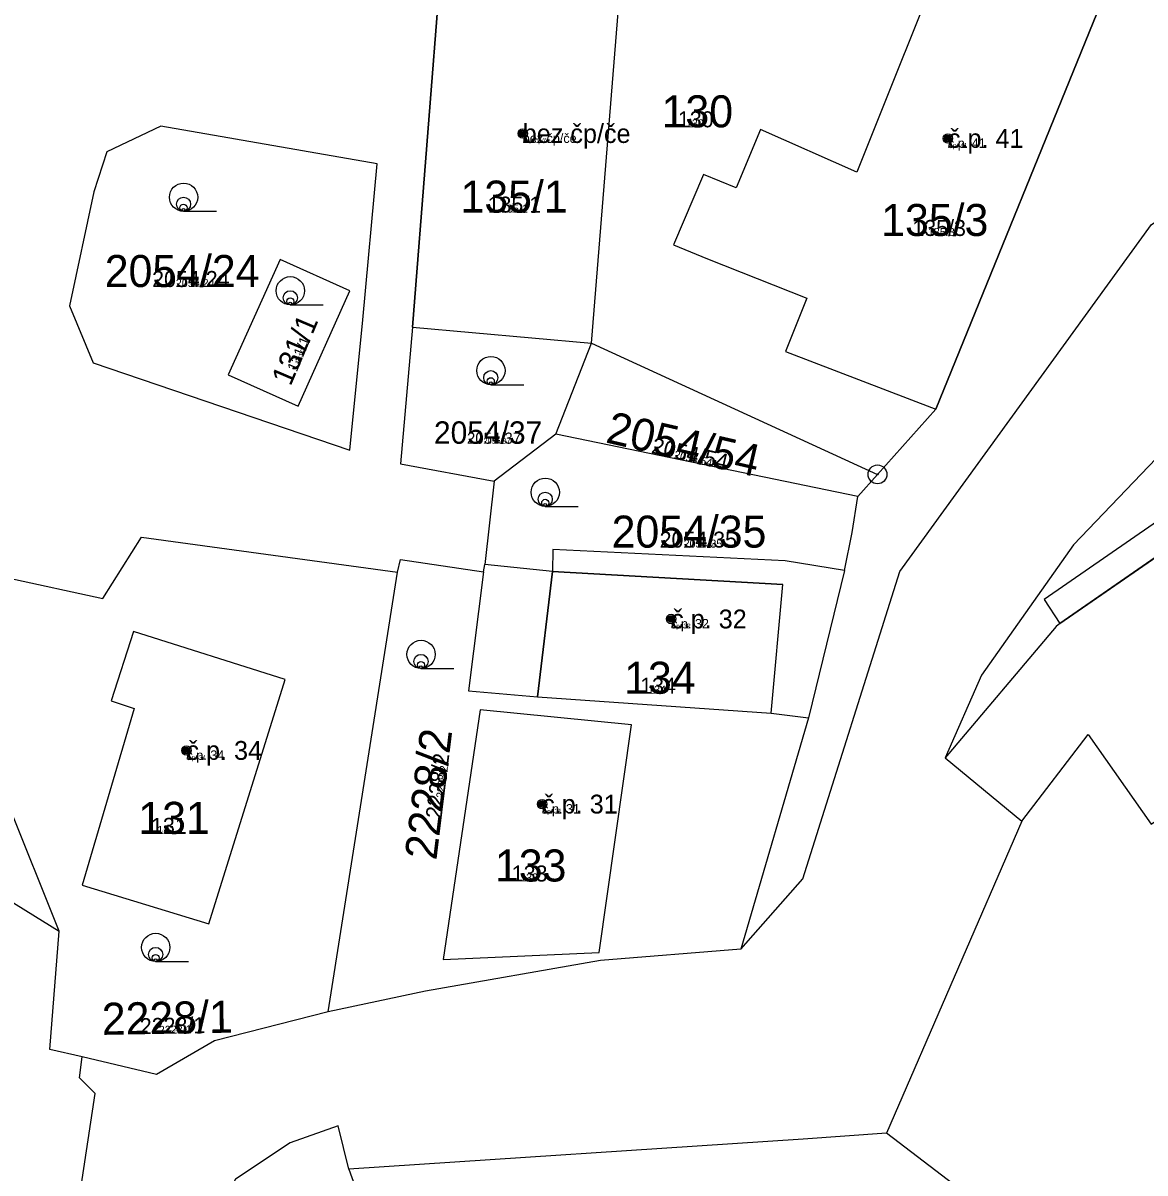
# Model space of a CAD drawing. Extents: x -744652 to -739090, y -980828 to -975855.
# Drawn here: x -742552.9 to -742493.3, y -978772.2 to -978711.1 of the extents above; entities that cross this region are included whole.
import ezdxf

# ---------------------------------------------------------------- set-up
doc = ezdxf.new("R2010")
doc.units = 0
for name, color, linetype in [('KAT_02_hranice parcel', 7, 'Continuous'), ('KAT_03_1000_st čísla parcelní', 7, 'Continuous'), ('KAT_03_1000_čísla parcelní', 7, 'Continuous'), ('KAT_03_1000_čísla popisná', 7, 'Continuous'), ('KAT_03_100_st čísla parcelní', 7, 'Continuous'), ('KAT_03_100_čísla parcelní', 7, 'Continuous'), ('KAT_03_100_čísla popisná', 7, 'Continuous'), ('KAT_03_250_st čísla parcelní', 7, 'Continuous'), ('KAT_03_250_čísla parcelní', 7, 'Continuous'), ('KAT_03_250_čísla popisná', 7, 'Continuous'), ('KAT_03_500_st čísla parcelní', 7, 'Continuous'), ('KAT_03_500_čísla parcelní', 7, 'Continuous'), ('KAT_03_500_čísla popisná', 7, 'Continuous'), ('KAT_04_vnitřní kresba', 7, 'Continuous'), ('KAT_05_1000_značky kultur', 7, 'Continuous'), ('KAT_05_100_značky kultur', 7, 'Continuous'), ('KAT_05_250_značky kultur', 7, 'Continuous'), ('KAT_05_500_značky kultur', 7, 'Continuous'), ('KAT_07_1000_značky budov', 7, 'Continuous'), ('KAT_07_100_značky budov', 7, 'Continuous'), ('KAT_07_500_značky budov', 7, 'Continuous'), ('KAT_11_značky bodu BP', 7, 'Continuous'), ('KAT_14_plocha_budovy', 7, 'Continuous')]:
    doc.layers.add(name, color=color, linetype=linetype)

msp = doc.modelspace()

# ---------------------------------------------------------------- linework, layer by layer
at = {"layer": 'KAT_02_hranice parcel'}
for p, q in [((-742532.24, -978727.28), (-742522.73, -978728.12)), ((-742524.62, -978732.95), (-742522.73, -978728.12)), ((-742522.73, -978728.12), (-742507.54, -978735.09)), ((-742507.54, -978735.09), (-742504.45, -978731.62)), ((-742524.62, -978732.95), (-742527.89, -978735.45)), ((-742508.58, -978736.26), (-742524.62, -978732.95)), ((-742508.58, -978736.26), (-742507.54, -978735.09)), ((-742527.89, -978735.45), (-742528.39, -978739.87)), ((-742528.47, -978740.27), (-742528.39, -978739.87)), ((-742536.72, -978763.63), (-742533.03, -978740.29)), ((-742509.3, -978740.19), (-742511.21, -978748.02)), ((-742511.21, -978748.02), (-742514.8, -978760.31)), ((-742503.95, -978750.15), (-742499.87, -978753.51)), ((-742499.87, -978753.51), (-742507.07, -978770.07)), ((-742554.18, -978757.39), (-742551, -978759.35)), ((-742488.77, -978784.01), (-742507.07, -978770.07)), ((-742535.61, -978771.98), (-742535.04, -978773.56))]:
    msp.add_line(p, q, dxfattribs=at)
for points in [[(-742514.8, -978760.31), (-742511.5, -978756.57), (-742506.35, -978740.24), (-742492.99, -978721.82), (-742477.74, -978711.95), (-742471.84, -978709.6), (-742471.81, -978707.76), (-742469.88, -978707.71), (-742450.51, -978700.27), (-742428.19, -978701.36), (-742428.2, -978700.54), (-742414.74, -978703.02)], [(-742503.55, -978706.34), (-742508.63, -978719.04), (-742513.76, -978716.77), (-742515.05, -978719.88), (-742516.78, -978719.16), (-742518.38, -978722.9), (-742516.57, -978723.65), (-742511.29, -978725.73), (-742512.43, -978728.57), (-742504.45, -978731.62)], [(-742503.55, -978706.34), (-742495.47, -978709.56), (-742504.45, -978731.62)], [(-742532.24, -978727.28), (-742530.72, -978707.92), (-742521.51, -978708.77)], [(-742522.73, -978728.12), (-742521.17, -978708.79), (-742521.51, -978708.77)], [(-742534.88, -978726.89), (-742534.12, -978718.6), (-742545.6, -978716.59), (-742548.46, -978717.96), (-742549.16, -978720.09), (-742550.45, -978726.14), (-742549.19, -978729.17), (-742535.56, -978733.81), (-742534.88, -978726.89)], [(-742470.25, -978719.38), (-742489.15, -978730.49), (-742497.14, -978738.84), (-742502.01, -978745.76), (-742503.95, -978750.15)], [(-742542.02, -978729.8), (-742538.31, -978731.47), (-742535.56, -978725.35), (-742539.27, -978723.68), (-742542.02, -978729.8)], [(-742465.82, -978724.74), (-742483.41, -978733.01), (-742484.4, -978733.67), (-742485.39, -978733.31), (-742486.83, -978733.72), (-742487.62, -978734.81), (-742487.68, -978735.97), (-742488.66, -978736.64), (-742489.52, -978735.39), (-742498.69, -978741.74), (-742497.86, -978743.01), (-742498.06, -978743.17), (-742503.95, -978750.15)], [(-742532.24, -978727.28), (-742532.87, -978734.53), (-742527.89, -978735.45)], [(-742499.87, -978753.51), (-742496.36, -978748.91), (-742493.01, -978753.67), (-742491.55, -978752.65), (-742480.55, -978768.62), (-742477.06, -978766.25), (-742476.32, -978767.3), (-742461.67, -978757.32), (-742471.99, -978742.58), (-742468.05, -978739.81), (-742463.71, -978737.68), (-742465.34, -978734.17), (-742463.7, -978728.64)], [(-742509.3, -978740.19), (-742508.88, -978738.17), (-742508.58, -978736.26)], [(-742551, -978759.35), (-742553.71, -978752.59), (-742554.39, -978748.63), (-742554.26, -978744.59), (-742553.72, -978740.59), (-742548.68, -978741.69), (-742546.62, -978738.42), (-742533.03, -978740.29)], [(-742509.3, -978740.19), (-742512.44, -978739.69), (-742524.78, -978739.08), (-742524.8, -978740.24), (-742528.39, -978739.87)], [(-742533.03, -978740.29), (-742532.87, -978739.61), (-742528.47, -978740.27)], [(-742528.47, -978740.27), (-742529.27, -978746.58), (-742525.59, -978746.9), (-742513.18, -978747.77), (-742511.21, -978748.02)], [(-742543.06, -978758.96), (-742539, -978745.98), (-742547.06, -978743.44), (-742548.24, -978747.11), (-742547.01, -978747.52), (-742549.77, -978756.9), (-742543.06, -978758.96)], [(-742520.61, -978748.39), (-742528.65, -978747.6), (-742530.61, -978760.86), (-742522.32, -978760.48), (-742520.61, -978748.39)], [(-742549.77, -978766.02), (-742551.5, -978765.64), (-742551, -978759.35)], [(-742514.8, -978760.31), (-742522.26, -978760.91), (-742531.54, -978762.54), (-742536.72, -978763.63)], [(-742536.72, -978763.63), (-742542.75, -978765.17), (-742545.83, -978766.96), (-742549.77, -978766.02)], [(-742550.52, -978777.46), (-742549.08, -978767.97), (-742549.92, -978767.13), (-742549.77, -978766.02)], [(-742535.61, -978771.98), (-742536.18, -978769.68), (-742538.73, -978770.59), (-742541.64, -978772.51), (-742542.72, -978774.57), (-742543.19, -978780.54), (-742542.48, -978785.35), (-742540.01, -978797.95), (-742544.04, -978799.67), (-742552.42, -978804.18), (-742552.86, -978804.25), (-742557.61, -978803.13), (-742558.73, -978802.65)], [(-742507.07, -978770.07), (-742511.49, -978770.39), (-742535.61, -978771.98)]]:
    msp.add_lwpolyline(points, dxfattribs=at)
at = {"layer": 'KAT_03_1000_čísla popisná'}
for centre in [(-742526.38, -978716.99), (-742526.38, -978716.99), (-742503.8, -978717.25), (-742503.8, -978717.25), (-742518.5, -978742.77), (-742518.5, -978742.77), (-742544.24, -978749.75), (-742544.24, -978749.75), (-742525.35, -978752.6), (-742525.35, -978752.6)]:
    msp.add_circle(centre, 0.25, dxfattribs=at)
at = {"layer": 'KAT_03_100_čísla popisná'}
for centre in [(-742526.38, -978716.99), (-742526.38, -978716.99), (-742503.8, -978717.25), (-742503.8, -978717.25), (-742518.5, -978742.77), (-742518.5, -978742.77), (-742544.24, -978749.75), (-742544.24, -978749.75), (-742525.35, -978752.6), (-742525.35, -978752.6)]:
    msp.add_circle(centre, 0.025, dxfattribs=at)
at = {"layer": 'KAT_03_250_čísla popisná'}
for centre in [(-742526.38, -978716.99), (-742526.38, -978716.99), (-742503.8, -978717.25), (-742503.8, -978717.25), (-742518.5, -978742.77), (-742518.5, -978742.77), (-742544.24, -978749.75), (-742544.24, -978749.75), (-742525.35, -978752.6), (-742525.35, -978752.6)]:
    msp.add_circle(centre, 0.0625, dxfattribs=at)
at = {"layer": 'KAT_03_500_čísla popisná'}
for centre in [(-742526.38, -978716.99), (-742526.38, -978716.99), (-742503.8, -978717.25), (-742503.8, -978717.25), (-742518.5, -978742.77), (-742518.5, -978742.77), (-742544.24, -978749.75), (-742544.24, -978749.75), (-742525.35, -978752.6), (-742525.35, -978752.6)]:
    msp.add_circle(centre, 0.125, dxfattribs=at)
at = {"layer": 'KAT_04_vnitřní kresba'}
for p, q in [((-742497.86, -978743.01), (-742488.66, -978736.64)), ((-742525.59, -978746.9), (-742524.8, -978740.24)), ((-742524.8, -978740.24), (-742512.56, -978740.94)), ((-742513.18, -978747.77), (-742512.56, -978740.94))]:
    msp.add_line(p, q, dxfattribs=at)
at = {"layer": 'KAT_05_1000_značky kultur'}
for p, q in [((-742544.393, -978721.12), (-742542.643, -978721.12)), ((-742538.723, -978726.09), (-742536.973, -978726.09)), ((-742528.073, -978730.33), (-742526.323, -978730.33)), ((-742525.183, -978736.79), (-742523.433, -978736.79)), ((-742531.783, -978745.4), (-742530.033, -978745.4)), ((-742545.873, -978760.96), (-742544.123, -978760.96))]:
    msp.add_line(p, q, dxfattribs=at)
for centre in [(-742544.393, -978720.37), (-742538.723, -978725.34), (-742528.073, -978729.58), (-742525.183, -978736.04), (-742531.783, -978744.65), (-742545.873, -978760.21)]:
    msp.add_circle(centre, 0.75, dxfattribs=at)
at = {"layer": 'KAT_05_100_značky kultur'}
for p, q in [((-742544.399, -978721.12), (-742544.224, -978721.12)), ((-742538.729, -978726.09), (-742538.554, -978726.09)), ((-742528.079, -978730.33), (-742527.904, -978730.33)), ((-742525.189, -978736.79), (-742525.014, -978736.79)), ((-742531.789, -978745.4), (-742531.614, -978745.4)), ((-742545.879, -978760.96), (-742545.704, -978760.96))]:
    msp.add_line(p, q, dxfattribs=at)
for centre in [(-742544.399, -978721.045), (-742538.729, -978726.015), (-742528.079, -978730.255), (-742525.189, -978736.715), (-742531.789, -978745.325), (-742545.879, -978760.885)]:
    msp.add_circle(centre, 0.075, dxfattribs=at)
at = {"layer": 'KAT_05_250_značky kultur'}
for p, q in [((-742544.398, -978721.12), (-742543.961, -978721.12)), ((-742538.728, -978726.09), (-742538.291, -978726.09)), ((-742528.078, -978730.33), (-742527.641, -978730.33)), ((-742525.188, -978736.79), (-742524.751, -978736.79)), ((-742531.788, -978745.4), (-742531.351, -978745.4)), ((-742545.878, -978760.96), (-742545.441, -978760.96))]:
    msp.add_line(p, q, dxfattribs=at)
for centre in [(-742544.398, -978720.932), (-742538.728, -978725.902), (-742528.078, -978730.142), (-742525.188, -978736.602), (-742531.788, -978745.212), (-742545.878, -978760.772)]:
    msp.add_circle(centre, 0.187, dxfattribs=at)
at = {"layer": 'KAT_05_500_značky kultur'}
for p, q in [((-742544.397, -978721.12), (-742543.522, -978721.12)), ((-742538.726, -978726.09), (-742537.851, -978726.09)), ((-742528.076, -978730.33), (-742527.201, -978730.33)), ((-742525.187, -978736.79), (-742524.312, -978736.79)), ((-742531.787, -978745.4), (-742530.912, -978745.4)), ((-742545.877, -978760.96), (-742545.002, -978760.96))]:
    msp.add_line(p, q, dxfattribs=at)
for centre in [(-742544.396, -978720.745), (-742538.726, -978725.715), (-742528.076, -978729.955), (-742525.186, -978736.415), (-742531.786, -978745.025), (-742545.876, -978760.585)]:
    msp.add_circle(centre, 0.375, dxfattribs=at)
at = {"layer": 'KAT_07_1000_značky budov'}
for centre in [(-742526.387, -978716.989), (-742503.807, -978717.249), (-742518.507, -978742.769), (-742544.247, -978749.749), (-742525.357, -978752.599)]:
    msp.add_circle(centre, 0.175, dxfattribs=at)
at = {"layer": 'KAT_07_100_značky budov'}
for centre in [(-742526.381, -978716.99), (-742503.801, -978717.25), (-742518.501, -978742.77), (-742544.241, -978749.75), (-742525.351, -978752.6)]:
    msp.add_circle(centre, 0.0175, dxfattribs=at)
at = {"layer": 'KAT_07_500_značky budov'}
for centre, radius in [((-742526.383, -978716.99), 0.0875), ((-742526.382, -978716.99), 0.0438), ((-742503.803, -978717.25), 0.0875), ((-742503.802, -978717.25), 0.0438), ((-742518.503, -978742.77), 0.0875), ((-742518.502, -978742.77), 0.0438), ((-742544.243, -978749.75), 0.0875), ((-742544.242, -978749.75), 0.0438), ((-742525.353, -978752.6), 0.0875), ((-742525.352, -978752.6), 0.0438)]:
    msp.add_circle(centre, radius, dxfattribs=at)
at = {"layer": 'KAT_11_značky bodu BP'}
for radius in [0.5, 0.0303]:
    msp.add_circle((-742507.54, -978735.09), radius, dxfattribs=at)
at = {"layer": 'KAT_14_plocha_budovy'}
for points in [[(-742516.78, -978719.16), (-742518.38, -978722.9), (-742516.57, -978723.65), (-742511.29, -978725.73), (-742512.43, -978728.57), (-742504.45, -978731.62), (-742495.47, -978709.56), (-742503.55, -978706.34), (-742508.63, -978719.04), (-742513.76, -978716.77), (-742515.05, -978719.88)], [(-742532.24, -978727.28), (-742522.73, -978728.12), (-742521.17, -978708.79), (-742521.51, -978708.77), (-742530.72, -978707.92)], [(-742503.95, -978750.15), (-742499.87, -978753.51), (-742496.36, -978748.91), (-742493.01, -978753.67), (-742491.55, -978752.65), (-742480.55, -978768.62), (-742477.06, -978766.25), (-742465.79, -978758.54), (-742483.41, -978733.01), (-742484.4, -978733.67), (-742485.39, -978733.31), (-742486.83, -978733.72), (-742487.62, -978734.81), (-742487.68, -978735.97), (-742488.66, -978736.64), (-742497.86, -978743.01), (-742498.06, -978743.17)], [(-742525.59, -978746.9), (-742513.18, -978747.77), (-742512.56, -978740.94), (-742524.8, -978740.24)], [(-742549.77, -978756.9), (-742543.06, -978758.96), (-742539, -978745.98), (-742547.06, -978743.44), (-742548.24, -978747.11), (-742547.01, -978747.52)], [(-742530.61, -978760.86), (-742522.32, -978760.48), (-742520.61, -978748.39), (-742528.65, -978747.6)]]:
    msp.add_lwpolyline(points, close=True, dxfattribs=at)

# ---------------------------------------------------------------- texts
at = {"layer": 'KAT_03_1000_st čísla parcelní'}
for s, p in [('135/1', (-742529.683, -978721.19)), ('135/3', (-742507.343, -978722.43)), ('134', (-742520.994, -978746.74)), ('131', (-742546.794, -978754.18)), ('133', (-742527.854, -978756.71))]:
    msp.add_text(s, height=1.7, dxfattribs=at).set_placement(p)
at = {"layer": 'KAT_03_1000_čísla parcelní'}
for s, height, p in [('130', 1.7, (-742519.004, -978716.66)), ('2054/24', 1.7, (-742548.578, -978725.14)), ('2054/37', 1.19, (-742531.096, -978733.465)), ('2054/35', 1.7, (-742521.658, -978738.98))]:
    msp.add_text(s, height=height, dxfattribs=at).set_placement(p)
for s, height, rotation, p in [('131/1', 1.14, 67, (-742538.711, -978730.444)), ('2054/54', 1.7, 347, (-742522.03, -978733.384)), ('2228/2', 1.7, 83, (-742530.969, -978755.614)), ('2228/1', 1.7, 1, (-742548.72, -978764.857))]:
    msp.add_text(s, height=height, rotation=rotation, dxfattribs=at).set_placement(p)
at = {"layer": 'KAT_03_1000_čísla popisná'}
for s, height, p in [('bez čp/če', 1, (-742526.38, -978717.49)), ('č.p. 41', 1, (-742503.8, -978717.75)), ('135/1', 0.017, (-742526.841, -978721.19)), ('135/3', 0.017, (-742504.07, -978722.43)), ('č.p. 32', 1, (-742518.5, -978743.27)), ('134', 0.017, (-742519.318, -978746.74)), ('č.p. 34', 1, (-742544.24, -978750.25)), ('č.p. 31', 1, (-742525.35, -978753.1)), ('131', 0.017, (-742545.462, -978754.18)), ('133', 0.017, (-742526.092, -978756.71))]:
    msp.add_text(s, height=height, dxfattribs=at).set_placement(p)
at = {"layer": 'KAT_03_100_st čísla parcelní'}
for s, p in [('135/1', (-742527.099, -978721.19)), ('135/3', (-742504.368, -978722.43)), ('134', (-742519.47, -978746.74)), ('131', (-742545.583, -978754.18)), ('133', (-742526.252, -978756.71))]:
    msp.add_text(s, height=0.17, dxfattribs=at).set_placement(p)
at = {"layer": 'KAT_03_100_čísla parcelní'}
for s, height, p in [('130', 0.17, (-742517.456, -978716.66)), ('2054/24', 0.17, (-742544.049, -978725.14)), ('2054/37', 0.119, (-742527.942, -978733.465)), ('2054/35', 0.17, (-742517.074, -978738.98))]:
    msp.add_text(s, height=height, dxfattribs=at).set_placement(p)
for s, height, rotation, p in [('131/1', 0.114, 67, (-742538.127, -978729.068)), ('2054/54', 0.17, 347, (-742517.64, -978734.397)), ('2228/2', 0.17, 83, (-742530.482, -978751.644)), ('2228/1', 0.17, 1, (-742545.101, -978764.794))]:
    msp.add_text(s, height=height, rotation=rotation, dxfattribs=at).set_placement(p)
at = {"layer": 'KAT_03_100_čísla popisná'}
for s, height, p in [('bez čp/če', 0.1, (-742526.38, -978717.49)), ('č.p. 41', 0.1, (-742503.8, -978717.75)), ('135/1', 0.0017, (-742526.815, -978721.19)), ('135/3', 0.0017, (-742504.04, -978722.43)), ('č.p. 32', 0.1, (-742518.5, -978743.27)), ('134', 0.0017, (-742519.303, -978746.74)), ('č.p. 34', 0.1, (-742544.24, -978750.25)), ('č.p. 31', 0.1, (-742525.35, -978753.1)), ('131', 0.0017, (-742545.45, -978754.18)), ('133', 0.0017, (-742526.076, -978756.71))]:
    msp.add_text(s, height=height, dxfattribs=at).set_placement(p)
at = {"layer": 'KAT_03_250_st čísla parcelní'}
for s, p in [('135/1', (-742527.53, -978721.19)), ('135/3', (-742504.863, -978722.43)), ('134', (-742519.724, -978746.74)), ('131', (-742545.785, -978754.18)), ('133', (-742526.519, -978756.71))]:
    msp.add_text(s, height=0.425, dxfattribs=at).set_placement(p)
at = {"layer": 'KAT_03_250_čísla parcelní'}
for s, height, p in [('130', 0.425, (-742517.714, -978716.66)), ('2054/24', 0.425, (-742544.804, -978725.14)), ('2054/37', 0.2975, (-742528.468, -978733.465)), ('2054/35', 0.425, (-742517.838, -978738.98))]:
    msp.add_text(s, height=height, dxfattribs=at).set_placement(p)
for s, height, rotation, p in [('131/1', 0.285, 67, (-742538.224, -978729.298)), ('2054/54', 0.425, 347, (-742518.372, -978734.229)), ('2228/2', 0.425, 83, (-742530.563, -978752.306)), ('2228/1', 0.425, 1, (-742545.704, -978764.804))]:
    msp.add_text(s, height=height, rotation=rotation, dxfattribs=at).set_placement(p)
at = {"layer": 'KAT_03_250_čísla popisná'}
for s, height, p in [('bez čp/če', 0.25, (-742526.38, -978717.49)), ('č.p. 41', 0.25, (-742503.8, -978717.75)), ('135/1', 0.00425, (-742526.819, -978721.19)), ('135/3', 0.00425, (-742504.045, -978722.43)), ('č.p. 32', 0.25, (-742518.5, -978743.27)), ('134', 0.00425, (-742519.305, -978746.74)), ('č.p. 34', 0.25, (-742544.24, -978750.25)), ('č.p. 31', 0.25, (-742525.35, -978753.1)), ('131', 0.00425, (-742545.452, -978754.18)), ('133', 0.00425, (-742526.078, -978756.71))]:
    msp.add_text(s, height=height, dxfattribs=at).set_placement(p)
at = {"layer": 'KAT_03_500_st čísla parcelní'}
for s, p in [('135/1', (-742528.247, -978721.19)), ('135/3', (-742505.69, -978722.43)), ('134', (-742520.147, -978746.74)), ('131', (-742546.121, -978754.18)), ('133', (-742526.964, -978756.71))]:
    msp.add_text(s, height=0.85, dxfattribs=at).set_placement(p)
at = {"layer": 'KAT_03_500_čísla parcelní'}
for s, height, p in [('130', 0.85, (-742518.144, -978716.66)), ('2054/24', 0.85, (-742546.062, -978725.14)), ('2054/37', 0.595, (-742529.344, -978733.465)), ('2054/35', 0.85, (-742519.112, -978738.98))]:
    msp.add_text(s, height=height, dxfattribs=at).set_placement(p)
for s, height, rotation, p in [('131/1', 0.57, 67, (-742538.387, -978729.68)), ('2054/54', 0.85, 347, (-742519.591, -978733.947)), ('2228/2', 0.85, 83, (-742530.698, -978753.409)), ('2228/1', 0.85, 1, (-742546.709, -978764.822))]:
    msp.add_text(s, height=height, rotation=rotation, dxfattribs=at).set_placement(p)
at = {"layer": 'KAT_03_500_čísla popisná'}
for s, height, p in [('bez čp/če', 0.5, (-742526.38, -978717.49)), ('č.p. 41', 0.5, (-742503.8, -978717.75)), ('135/1', 0.0085, (-742526.826, -978721.19)), ('135/3', 0.0085, (-742504.053, -978722.43)), ('č.p. 32', 0.5, (-742518.5, -978743.27)), ('134', 0.0085, (-742519.309, -978746.74)), ('č.p. 34', 0.5, (-742544.24, -978750.25)), ('č.p. 31', 0.5, (-742525.35, -978753.1)), ('131', 0.0085, (-742545.456, -978754.18)), ('133', 0.0085, (-742526.083, -978756.71))]:
    msp.add_text(s, height=height, dxfattribs=at).set_placement(p)

doc.saveas('drawing.dxf')
